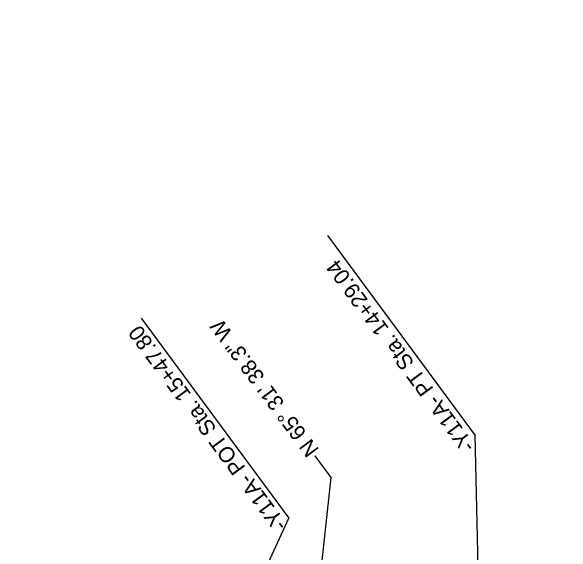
# Model space of a CAD drawing. Extents: x 472216 to 481979, y 489069 to 507339.
# Drawn here: x 475503.5 to 475755.7, y 502706.2 to 502949.8 of the extents above; entities that cross this region are included whole.
import ezdxf

# ---------------------------------------------------------------- set-up
doc = ezdxf.new("R2010")
doc.units = 0
for name, color, linetype in [('Old_Level_12', 7, 'Continuous'), ('Prop Drainage Structure Pipe RCP 15in Class III Label', 7, 'Continuous'), ('Prop Drainage Structure Pipe RCP 24in Class III Label', 7, 'Continuous'), ('Prop Erosion Embankment Toe Protection CELL', 7, 'Continuous'), ('Prop Erosion Embankment Toe Protection Label', 7, 'Continuous'), ('Sheet North Arrow Point CELL', 7, 'Continuous'), ('Sheet Plan And Profile CELL', 7, 'Continuous')]:
    doc.layers.add(name, color=color, linetype=linetype)

msp = doc.modelspace()

# ---------------------------------------------------------------- linework, layer by layer
at = {"layer": 'Old_Level_12'}
for p, q in [((475645.79, 502849), (475712.26, 502758.99)), ((475561.97, 502811.83), (475628.44, 502721.82)), ((475715.14, 502626.15), (475712.26, 502758.99)), ((475640.18, 502749.79), (475647.35, 502740.08)), ((475647.35, 502740.08), (475638.64, 502659.47)), ((475607.05, 502675.35), (475628.44, 502721.82))]:
    msp.add_line(p, q, dxfattribs=at)
at = {"layer": 'Prop Drainage Structure Pipe RCP 15in Class III Label'}
for radius in [2336, 2324]:
    msp.add_arc((473624.13, 501255.38), radius, 25.1104, 43.06144, dxfattribs=at)
at = {"layer": 'Prop Drainage Structure Pipe RCP 24in Class III Label'}
for radius, start, end in [(2348, 26.36139, 43.06144), (2300, 33.44784, 43.06537), (2300, 33.44784, 43.06144)]:
    msp.add_arc((473624.13, 501255.38), radius, start, end, dxfattribs=at)
at = {"layer": 'Prop Erosion Embankment Toe Protection CELL'}
for radius, start, end in [(2353, 25.8357, 43.06144), (2295, 33.45244, 43.06537)]:
    msp.add_arc((473624.13, 501255.38), radius, start, end, dxfattribs=at)
at = {"layer": 'Prop Erosion Embankment Toe Protection Label'}
msp.add_arc((473624.13, 501255.38), 2312, 25.1104, 43.06144, dxfattribs=at)
at = {"layer": 'Sheet North Arrow Point CELL'}
for centre, radius, start, end in [((474253.94, 501667.1), 1500, 26.80164, 58.77708), ((473624.13, 501255.38), 2330, 23.81642, 43.37358)]:
    msp.add_arc(centre, radius, start, end, dxfattribs=at)

# ---------------------------------------------------------------- texts
at = {"layer": 'Old_Level_12'}
for s, p in [('-Y11A- PT Sta. 14+29.04', (475712.64, 502754.43)), ('-Y11A- POT Sta. 15+47.80', (475628.02, 502719))]:
    msp.add_text(s, height=7, rotation=126.4463, dxfattribs=at).set_placement(p)
at = {"layer": 'Sheet Plan And Profile CELL'}
msp.add_text('N 65%%d 31\' 38.3" W', height=7, rotation=126.6395, dxfattribs=at).set_placement((475642.29, 502752.64))

doc.saveas('drawing.dxf')
